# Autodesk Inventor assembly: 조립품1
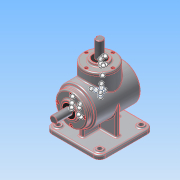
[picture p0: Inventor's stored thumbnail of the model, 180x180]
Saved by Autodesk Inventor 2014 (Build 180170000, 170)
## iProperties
Created: 2015-07
Part Number: 조립품1
Document SubType Name: Assembly
Designer: net
Author: net
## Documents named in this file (14)
- C:\Users\net\Desktop\450705V1028\답안조립품.iam
- C:\Users\net\Desktop\450705V1028\본체.ipt
- C:\Users\net\Desktop\450705V1028\커버.ipt
- C:\Users\net\Desktop\450705V1028\베어링 6203.ipt
- C:\Users\net\Desktop\450705V1028\서브 축.ipt
- 서브 축.ipt
- C:\Users\net\Desktop\450705V1028\키 4x4.ipt
- C:\Users\net\Desktop\450705V1028\서브 베벨기어.ipt
- C:\Users\net\Desktop\450705V1028\메인 축.ipt
- 메인 축.ipt
- C:\Users\net\Desktop\450705V1028\키 5x5.ipt
- C:\Users\net\Desktop\450705V1028\메인 베벨기어.ipt
- C:\Users\net\Desktop\450705V1028\오일실.ipt
- C:\Users\net\Desktop\450705V1028\M4.ipt
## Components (8 placed, 1 different names)
1. M4:1
2. M4:3
3. M4:4
4. M4:5
5. M4:2
6. M4:6
7. M4:7
8. M4:8
